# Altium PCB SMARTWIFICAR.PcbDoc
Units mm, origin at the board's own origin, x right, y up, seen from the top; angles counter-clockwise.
Board outline 20 x 36.25 mm, 2 copper layers (Top Layer, Bottom Layer); 33 components, 21 nets, 122 pads, 17 vias.
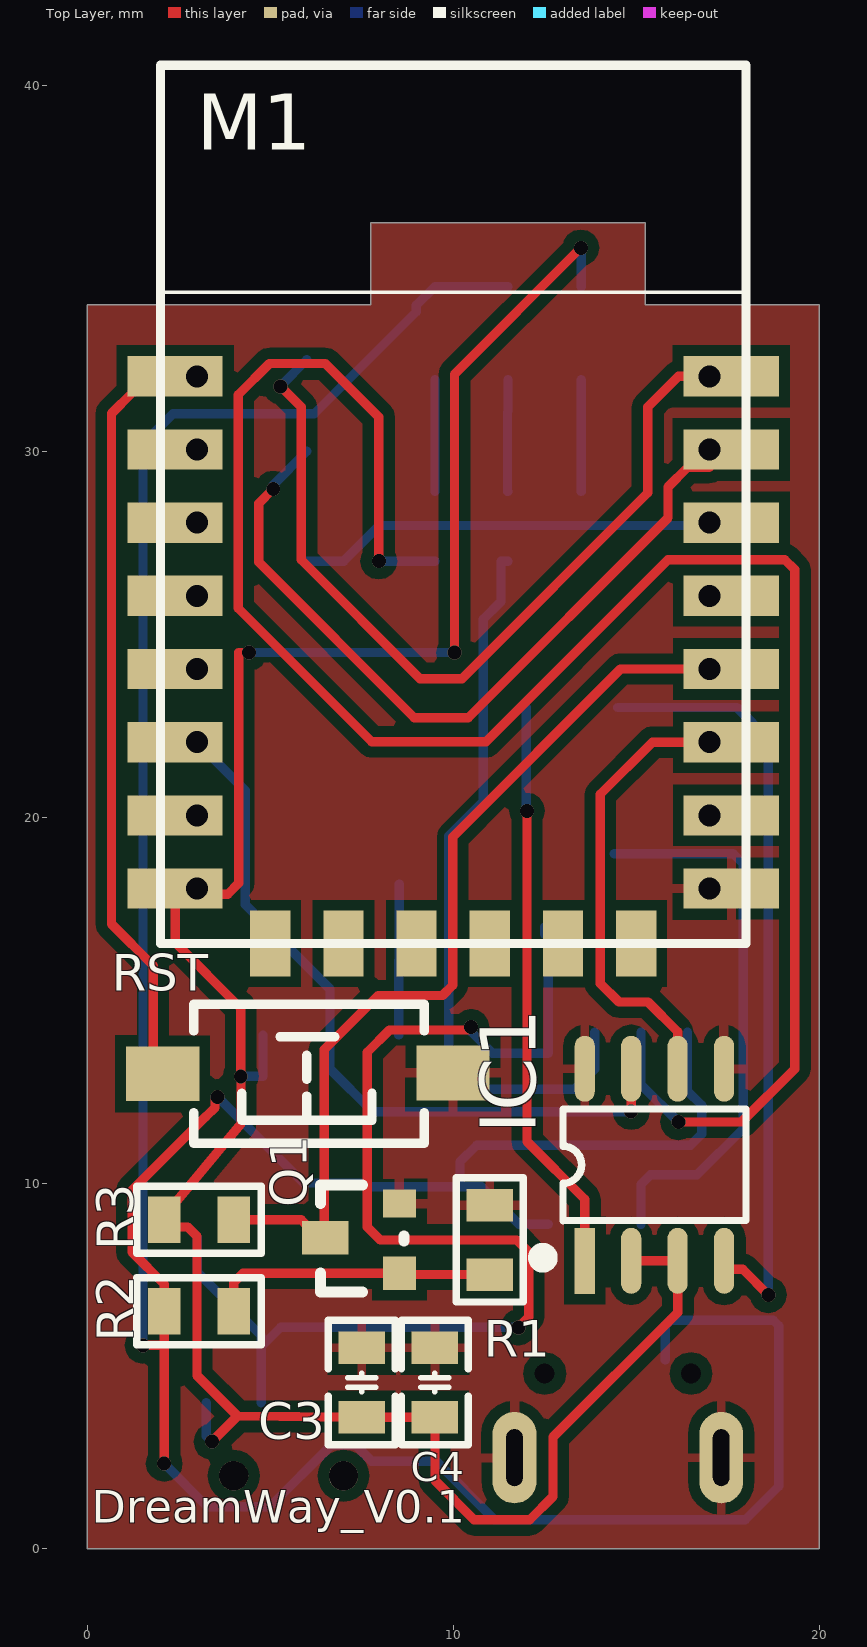
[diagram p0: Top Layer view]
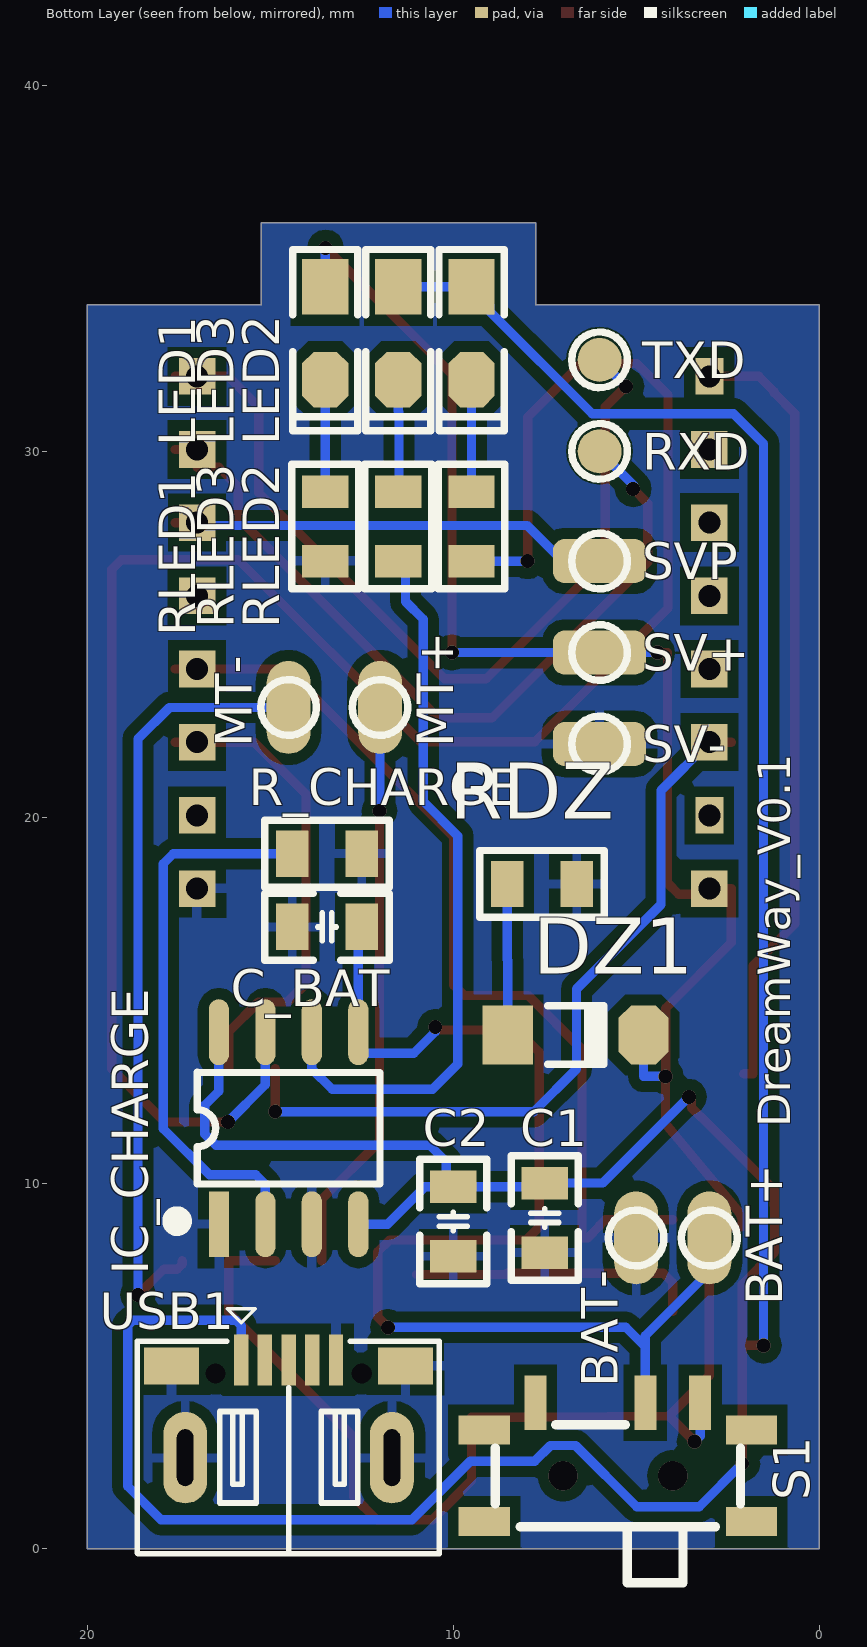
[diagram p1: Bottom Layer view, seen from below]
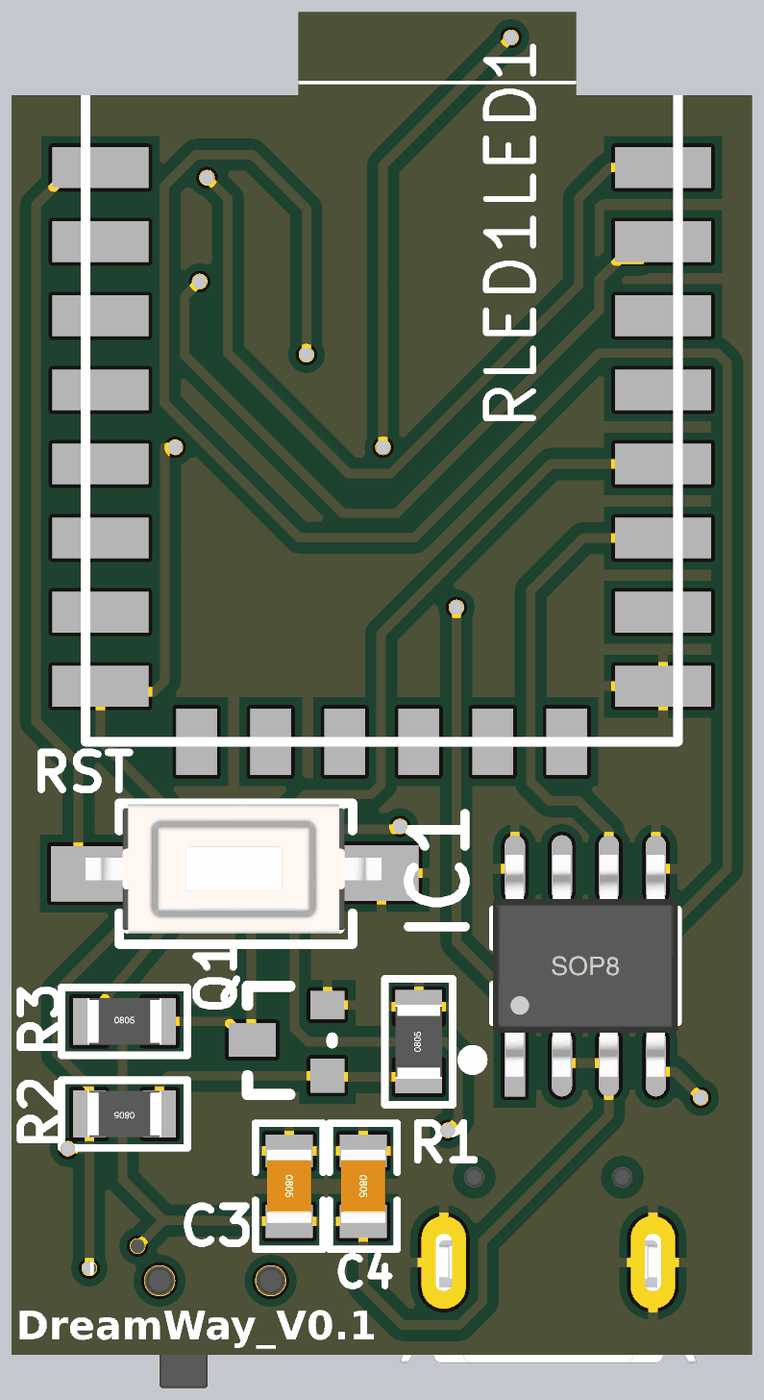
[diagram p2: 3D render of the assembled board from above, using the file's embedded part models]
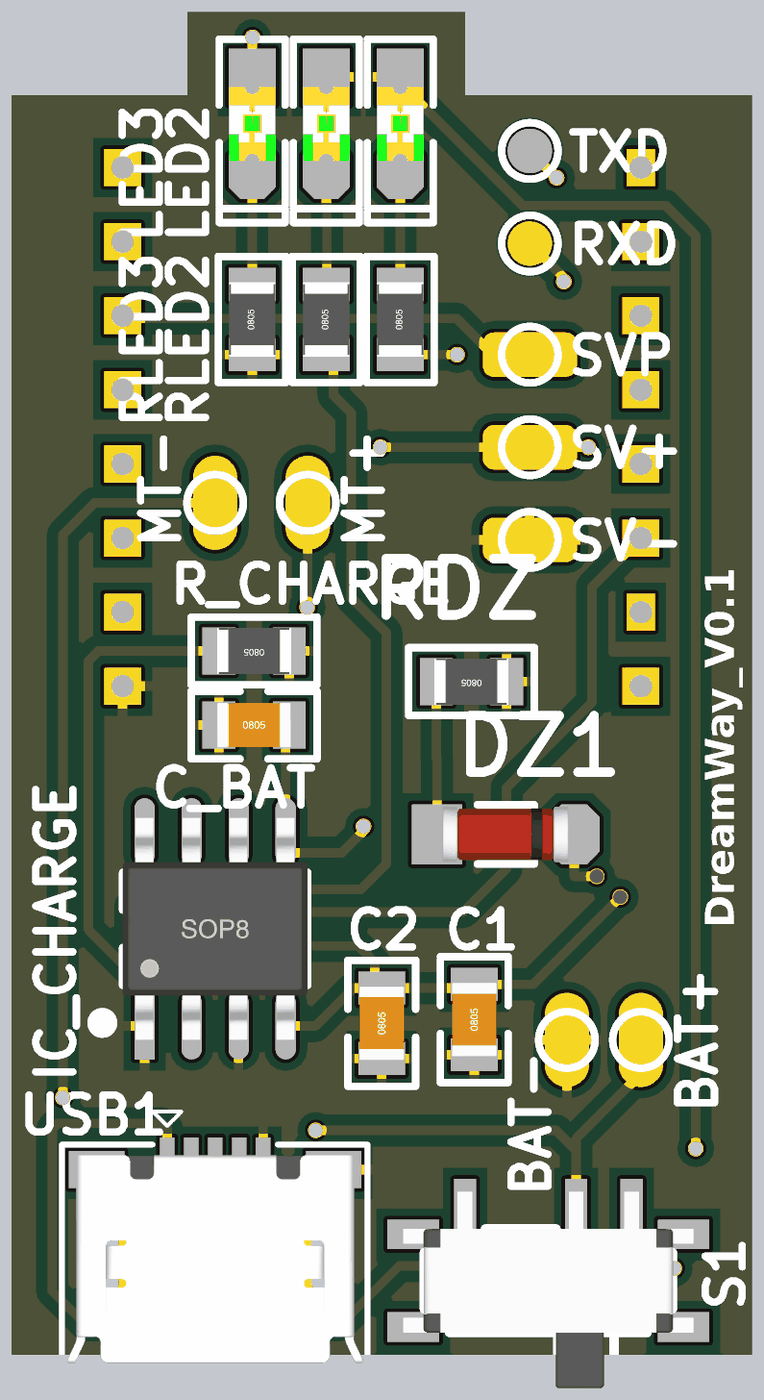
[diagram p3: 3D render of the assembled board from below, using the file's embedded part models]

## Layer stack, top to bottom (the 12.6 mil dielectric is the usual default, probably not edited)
Top Solder: solder mask 0.0102, Solder Resist, Dk 3.5
Top Layer: signal copper 0.0356
Dielectric 1: dielectric 0.32, FR-4, Dk 4.8
Bottom Layer: signal copper 0.0356
Bottom Solder: solder mask 0.0102, Solder Resist, Dk 3.5

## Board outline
0,0 0,34 7.75,34 7.75,36.25 15.25,36.25 15.25,34 20,34 20,0

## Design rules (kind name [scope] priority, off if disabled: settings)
Clearance [All] p1: gap=0.3 ignorepadtopadclearanceinfootprint=FALSE
HoleSize [All] p1: absolutevalues=TRUE maxlimit=2.54 minlimit=0.3 maxpercent=80.000 minpercent=20.000
PlaneConnect [All] p1: planeconnectstyle=Relief reliefexpansion=0.508 reliefentries=4 reliefconductorwidth=0.3 reliefairgap=0.3
PolygonConnect [All] p1: connectstyle=Relief reliefconductorwidth=0.254 reliefentries=4 polygonreliefangle="90 Angle" airgapwidth=0.3
RoutingVias [All] p1: holewidth=0.381 width=0.381 viastyle="Through Hole" minholewidth=0.381 minwidth=0.381 maxholewidth=0.711 maxwidth=1.27
SolderMaskExpansion [All] p1: expansion=0.102 istentingtop=FALSE
UnRoutedNet [All] p1: checkbadconnections=TRUE
Width [All] p1: maxlimit=0.508 minlimit=0.152 preferedwidth=0.254
27 further rules are at their usual default settings.

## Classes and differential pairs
component class Motor: IC1
component class IO_CONN: BAT+ BAT- MT+ RXD SV+ SV- SVP TXD
component class Control: M1 Q1 R1 R2 R3 RST
component class Charge: C1 C2 C3 C4 C_BAT DZ1 IC_CHARGE LED1 LED2 LED3 R_CHARGE RDZ RLED1 RLED2 RLED3 S1 USB1

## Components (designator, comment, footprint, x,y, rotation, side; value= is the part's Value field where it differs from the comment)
BAT+ "TEST" "TEST 1.2"#1 3,8.5 r180 bottom
BAT- "TEST" "TEST 1.2"#1 5,8.5 r180 bottom
C1 "106" "C 0805_L" 7.5,9.05 r90 bottom
C2 "104" "C 0805_L" 10,8.95 r90 bottom
C3 "106" "C 0805_L" 7.5,4.55 r270 top
C4 "104" "C 0805_L" 9.5,4.55 r270 top
C_BAT "106" "C 0805_L" 13.45,17 r180 bottom
DZ1 "ZMM3V3" "MINI_MELF (LL34)" 6.655,14.05 r180 bottom
IC1 "L9110" SOP8_N 15.5,10.5 r90 top
IC_CHARGE "TP4056" SOP8_N 14.5,11.5 r90 bottom
LED1 "BLUE" "LED 0805B" 13.5,33.23 r270 bottom
LED2 "RED" "LED 0805R" 9.5,33.23 r270 bottom
LED3 "GREEN" "LED 0805G" 11.5,33.23 r270 bottom
M1 "ESP-12E&F Module F" "ESP-12E&F Module" 10,24.3 r0 top
MT+ "TEST" "TEST 1.2"#1 12,23 r0 bottom
MT- "TEST" "TEST 1.2"#1 14.5,23 r180 bottom
Q1 "BCP68" SOT-23 5.477,6.322 r90 top
R1 "10K" "R 0805_L" 11,8.45 r90 top
R2 "10K" "R 0805_L" 3.05,6.5 r180 top
R3 "10K" "R 0805_L" 3.05,9 r0 top
R_CHARGE "1.2K" "R 0805_L" 13.45,19 r0 bottom
RDZ "1.2K" "R 0805_L" 7.575,18.175 r0 bottom
RLED1 "1.2K" "R 0805_L" 13.5,27.95 r90 bottom
RLED2 "1.2K" "R 0805_L" 9.5,27.95 r90 bottom
RLED3 "1.2K" "R 0805_L" 11.5,27.95 r90 bottom
RST "3x6x5" "TSW SMD-3*6*2.5" 6,12.987 r180 top
RXD "TEST" "TEST 1.2"#2 6,30 r0 bottom
S1 "SS-12F23" MSK-12C01-07 5.5,2 r180 bottom
SV+ "TEST" "TEST 1.2"#3 6,24.5 r270 bottom
SV- "TEST" "TEST 1.2"#3 6,22 r270 bottom
SVP "TEST" "TEST 1.2"#3 6,27 r270 bottom
TXD "TEST" "TEST 1.2"#4 6,32.5 r0 bottom
USB1 "USB-5P" USB-MICRO_B 14.5,2.5 r180 bottom

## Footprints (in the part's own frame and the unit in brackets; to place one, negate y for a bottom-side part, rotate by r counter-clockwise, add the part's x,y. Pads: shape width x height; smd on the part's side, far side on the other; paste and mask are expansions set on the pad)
"C 0805_L" [mil] "无极性贴片电容                                        淘宝ID:黄晶宝石"
  rect 35x50 smd: 1(-37.4,0) 2(37.4,0)
  silkscreen extent -67,-36 67,36, body extent -39,-24 39,24, height 20
"ESP-12E&F Module" [mm]
  rect 2.6x1.1 smd: 1(-7.6,7.75) 2(-7.6,5.75) 3(-7.6,3.75) 4(-7.6,1.75) 5(-7.6,-0.25) 6(-7.6,-2.25) 7(-7.6,-4.25) 8(-7.6,-6.25) 15(7.6,-6.25) 16(7.6,-4.25) 17(7.6,-2.25) 18(7.6,-0.25) 19(7.6,1.75) 20(7.6,3.75) 21(7.6,5.75) 22(7.6,7.75)
  rect 0.762x1 hole 0.6: 1(-7,7.75) 7(-7,-4.25)
  rect 0.762x1 / inner rect 0.762x1 / far side rect 1x1 hole 0.6: 2(-7,5.75) 3(-7,3.75) 4(-7,1.75) 5(-7,-0.25) 6(-7,-2.25) 8(-7,-6.25) 15(7,-6.25) 16(7,-4.25) 17(7,-2.25) 18(7,-0.25) 19(7,1.75) 20(7,3.75) 21(7,5.75) 22(7,7.75)
  rect 1.1x1.8 smd: 9(-5,-7.75) 10(-3,-7.75) 11(-1,-7.75) 12(1,-7.75) 13(3,-7.75) 14(5,-7.75)
  silkscreen extent -8,-7.75 8,16.25
"LED 0805B" [mil] "蓝色0805LED                                    淘宝ID:黄晶宝石"
  rect 60x50 smd: 1(-50,0)
  oct 60x50 smd: 2(50,0)
  silkscreen extent -90,-35 105,35, body extent -39,-25 39,25, height 32
"LED 0805G" [mil] "绿色0805LED                              淘宝ID:黄晶宝石"
  rect 60x50 smd: 1(-50,0)
  oct 60x50 smd: 2(50,0)
  silkscreen extent -90,-35 105,35, body extent -39,-25 39,25, height 32
"LED 0805R" [mil] "红色0805LED                                       淘宝ID:黄晶宝石"
  rect 60x50 smd: 1(-50,0)
  oct 60x50 smd: 2(50,0)
  silkscreen extent -90,-35 105,35, body extent -39,-25 39,25, height 32
"MINI_MELF (LL34)" [mm] "1.5*3.4mm(直径，脚距）"
  rect 1.37x1.62 smd: 1(-1.855,0)
  oct 1.37x1.62 smd: 2(1.855,0)
  silkscreen extent -0.76,-0.8 0.78,0.8, body extent -1.7,-0.75 1.7,0.75, height 1.5
MSK-12C01-07 [mm] "6.7*2.8*1.5mm(长宽高）      淘宝ID:黄晶宝石"
  rect 1.4x0.8 smd: 0(-3.65,-1.25) 0(-3.65,1.25) 0(3.65,-1.25) 0(3.65,1.25)
  rect 0.6x1.5 smd: 1(-2.25,1.996) 2(0.75,1.996) 3(2.25,1.996)
  round 0.8 hole 0.8: " "(-1.5,0) " "(1.5,0)
  silkscreen extent -3.35,-2.92 3.35,1.4, body extent -3.92,-2.9 3.92,2.4, height 1.5
"R 0805_L" [mil] "1/8W贴片电阻"
  rect 35x50 smd: 1(-37.41,0) 2(37.4,0)
  silkscreen extent -67,-36 67,36, body extent -39,-25 39,25, height 20
SOP8_N [mm] "5*6*1.8mm（长宽高）封装库来自淘宝卖家 ID：黄晶宝石"
  rect 1.8x0.55 smd: 1(-2.625,1.905)
  oval 1.8x0.55 smd: 2(-2.625,0.635) 3(-2.625,-0.635) 4(-2.625,-1.905) 5(2.625,-1.905) 6(2.625,-0.635) 7(2.625,0.635) 8(2.625,1.905)
  silkscreen extent -2.69,-2.5 1.52,3.2, body extent -3,-2.5 3,2.5, height 1.9
SOT-23 [mil] "封装库来自淘宝卖家 ID：黄晶宝石"
  rect 36x36 smd: 1(47.75,-120.28)
  rect 30x36 smd: 2(122.75,-120.28)
  rect 36x50 smd: 3(85.75,-40.28)
  silkscreen extent 28,-125 143,-35
"TEST 1.2"#1 [mm] "测试点1.2mm"
  oval 1.2x2.54 smd paste-1.2: 1(0,0)
  silkscreen extent -0.76,-0.76 0.76,0.76
"TEST 1.2"#2 [mm] "测试点1.2mm"
  round 1.2 smd paste-1.2: 1(0,0)
  silkscreen extent -0.76,-0.76 0.76,0.76
"TEST 1.2"#3 [mm] "测试点1.2mm"
  rrect50% 1.2x2.54 smd paste-1.2: 1(0,0)
  silkscreen extent -0.76,-0.76 0.76,0.76
"TEST 1.2"#4 [mm] "测试点1.2mm"
  round 1.2 smd paste+0: 1(0,0)
  silkscreen extent -0.76,-0.76 0.76,0.76
"TSW SMD-3*6*2.5" [mm] "3*6*2.5mm"
  rect 2x1.5 smd: 1(-3.996,-0.02) 2(3.937,0)
  silkscreen extent -3.21,-1.9 3.09,1.9, body extent -4,-1.88 4,1.62, height 2.59
USB-MICRO_B [mm] "micro型USB ，5.9*8.2*2.5mm 淘宝ID:黄晶宝石   店铺网址:https://shop463601444.taobao.com"
  round 0 hole 0.55 unplated: 0(-2,2.294) 0(2,2.294)
  rect 0.394x1.4 smd: 1(-1.295,2.667) 2(-0.648,2.667) 3(0,2.667) 4(0.648,2.667) 5(1.295,2.667)
  rect 1.5x1 smd: 5(-3.2,2.5) 5(3.2,2.5)
  oval 1.2x2.5 hole 0.45 slot 1.55 at 90 deg: 5(-2.825,-0.006) 5(2.825,-0.006)
  silkscreen extent -4.14,-2.63 4.11,4.06, body extent -4,-2.72 4,2.88, height 2.8

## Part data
BAT+ BAT- MT+ MT- RXD SV+ SV- SVP TXD: "测试点"
C1 C2 C3 C4 C_BAT: library part C, "贴片电容"
DZ1: library part 1N4619, "3V/0.5W稳压管"
IC1: "直流电机控制芯片"
IC_CHARGE: "锂电池充电管理"
LED1 LED2 LED3: library part LED-SMD, "贴片LED"
M1: library part "ESP-12E&F Module", "ESP-12E&F Module"
Q1: "NPN三极管"
R1 R2 R3 R_CHARGE RDZ RLED1 RLED2 RLED3: library part R, "贴片电阻"
RST: library part "TSW 3x6", "3x6轻触开关"
S1: library part SSW-1P, "1路波动开关"
USB1: "微型USB母座"

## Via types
v1: diameter 0.381, hole 0.381, Top Layer to Bottom Layer, 17 vias

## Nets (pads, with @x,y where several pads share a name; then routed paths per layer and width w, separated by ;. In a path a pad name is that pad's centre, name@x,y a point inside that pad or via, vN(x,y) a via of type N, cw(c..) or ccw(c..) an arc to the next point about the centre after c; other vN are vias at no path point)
3V3: C3.2 C4.2 DZ1.2 IC1.2 IC1.3 LED1.1 M1.8 R3.1 S1.3 SV+.1 | length 68.9
  Top Layer w0.254: v1(3.405,2.935) 4.104,3.633 ; v1(4.421,24.499) 4.142,24.499 4.142,18.2 3.837,17.895 3,17.895 3,18.05 2.4,18.05 2.4,16.575 4.193,14.782 v1(4.193,12.917) 4.2,12.909 4.2,11.621 2.182,9.2 R3.1 2.1,8.802 2.745,8.802 2.999,8.548 2.999,4.738 4.104,3.633 ; v1(10.035,24.5) 10.035,32.108 v1(13.489,35.563) ; IC1.2 IC1.3 16.135,6.465 12.727,3.057 12.727,1.436 12.092,0.801 10.568,0.801 9.5,1.869 C4.2 C3.2 4.104,3.633
  Bottom Layer w0.254: S1.3 3.25,3.09 v1(3.405,2.935) ; v1(4.193,12.917) 4.8,12.917 DZ1.2 ; v1(4.421,24.499) SV+.1 v1(10.035,24.5) ; v1(13.489,35.563) 13.5,35.552 LED1.1
BAT+: BAT+.1 C_BAT.2 IC_CHARGE.5 S1.2 | length 33.2
  Top Layer w0.254: v1(10.492,14.263) 10.416,14.187 8.257,14.187 7.647,13.577 7.647,8.802 8.003,8.446 11.737,8.446 12.062,8.121 12.062,6.338 v1(11.783,6.059)
  Bottom Layer w0.254: BAT+.1 3,7.58 4.75,5.83 4.75,5.524 ; S1.2 4.75,5.524 ; v1(10.492,14.263) 10.492,14.136 11.076,13.552 12.595,13.552 IC_CHARGE.5 12.595,16.708 12.5,16.803 C_BAT.2 ; v1(11.783,6.059) 5.285,6.059 4.75,5.524
BAT-: BAT-.1 C1.1 C2.1 C3.1 C4.1 C_BAT.1 IC1.5 IC1.8 IC_CHARGE.1 IC_CHARGE.3 M1.15 Q1.2 R1.2 R_CHARGE.1 RDZ.1 RLED1.1 RST.1 SV-.1 USB1.5
NetDZ1_1: DZ1.1 RDZ.2 | length 4.1
  Bottom Layer w0.254: DZ1.1 8.51,16.092 8.525,16.107 RDZ.2
NetIC1_1: IC1.1 MT+.1 | length 15.8
  Top Layer w0.254: v1(12.016,20.175) 12.016,11.139 13.595,9.56 IC1.1
  Bottom Layer w0.254: MT+.1 12,20.191 v1(12.016,20.175)
NetIC1_4: IC1.4 MT-.1 | length 21.3
  Top Layer w0.254: IC1.4 17.405,7.782 17.542,7.645 17.912,7.645 v1(18.614,6.943)
  Bottom Layer w0.254: MT-.1 17.757,23 18.614,22.143 v1(18.614,6.943)
NetIC1_6: IC1.6 M1.17 | length 13
  Top Layer w0.254: IC1.6 16.135,14.136 15.321,14.95 14.529,14.95 14.022,15.457 14.022,20.625 15.448,22.05 17,22.05 17.299,22.05 M1.17@17.6,22.05
NetIC1_7: IC1.7 M1.6 | length 20.9
  Top Layer w0.254: M1.6@2.4,22.05 M1.6@3,22.05 ; v1(14.865,11.952) IC1.7
  Bottom Layer w0.254: M1.6@3,22.05 4.32,20.73 4.32,17.616 6.631,15.304 6.631,13.12 7.799,11.952 v1(14.865,11.952)
NetIC_CHARGE_2: IC_CHARGE.2 R_CHARGE.2 | length 15.4
  Bottom Layer w0.254: R_CHARGE.2 17.654,19 17.927,18.727 17.927,11.487 16.664,10.224 15.394,10.224 15.135,9.965 IC_CHARGE.2
NetIC_CHARGE_6: IC_CHARGE.6 RLED3.1 | length 20
  Bottom Layer w0.254: RLED3.1 11.305,27 11.305,25.896 10.822,25.414 10.822,20.435 9.874,19.487 9.874,13.255 10.568,12.561 13.306,12.561 13.865,13.12 IC_CHARGE.6
NetIC_CHARGE_7: IC_CHARGE.7 RLED2.1 | length 55.3
  Top Layer w0.254: v1(7.966,27) 7.966,30.937 6.504,32.399 4.98,32.399 4.127,31.546 4.127,25.708 7.774,22.061 10.894,22.061 15.873,27.039 19.065,27.039 19.331,26.773 19.331,13.12 17.881,11.67 v1(16.156,11.67)
  Bottom Layer w0.254: v1(7.966,27) RLED2.1 ; IC_CHARGE.7 15.135,12.691 v1(16.156,11.67)
NetLED1_2: LED1.2 RLED1.2 | length 3.1
  Bottom Layer w0.254: RLED1.2 LED1.2
NetLED2_2: LED2.2 RLED2.2 | length 3.1
  Bottom Layer w0.254: RLED2.2 LED2.2
NetLED3_2: LED3.2 RLED3.2 | length 3.1
  Bottom Layer w0.254: RLED3.2 11.482,28.9 11.482,31.078 11.5,31.095 LED3.2
NetM1_1: M1.1 RST.2 | length 21.6
  Top Layer w0.254: RST.2 1.805,12.987 1.805,15.939 0.662,17.082 0.662,31.037 1.227,31.602 1.227,31.627 1.65,32.05 2.4,32.05 M1.1@3,32.05
NetM1_18: M1.18 Q1.3 R3.2 | length 25.7
  Top Layer w0.254: R3.2 5.843,9 5.992,8.851 5.992,8.83 6.322,8.5 Q1.3 ; Q1.3@6.479,8.5 6.479,13.653 7.952,15.127 9.704,15.127 9.984,15.406 9.984,19.462 14.572,24.05 17,24.05 17.299,24.05 M1.18@17.6,24.05
NetM1_20: M1.20 SVP.1 | length 12
  Top Layer w0.254: M1.20@17,28.05 M1.20@17.6,28.05
  Bottom Layer w0.254: SVP.1 7.005,27 7.98,27.975 16.925,27.975 M1.20@17,28.05
NetM1_21: M1.21 RXD.1 | length 22.1
  Top Layer w0.254: v1(5.082,28.974) 4.681,28.574 4.681,26.977 8.937,22.721 10.413,22.721 15.873,28.181 15.873,29.027 16.41,29.564 17,29.564 17,30.05 M1.21@17.6,30.05
  Bottom Layer w0.254: v1(5.082,28.974) 5.082,29.082 RXD.1
NetM1_22: M1.22 TXD.1 | length 23.9
  Top Layer w0.254: v1(5.278,31.778) 5.843,31.213 5.843,27.04 9.095,23.788 10.239,23.788 15.319,28.868 15.319,31.213 16.156,32.05 17,32.05 17.299,32.05 M1.22@17.6,32.05
  Bottom Layer w0.254: v1(5.278,31.778) TXD.1
NetQ1_1: Q1.1 R1.1 R2.1 | length 7.9
  Top Layer w0.254: R2.1 4,7.278 4.257,7.535 Q1.1 8.567,7.5 R1.1
USB5V: C1.2 C2.2 IC_CHARGE.4 IC_CHARGE.8 LED2.1 LED3.1 R2.2 USB1.1 | length 97.2
  Top Layer w0.254: v1(1.519,5.566) 2.1,5.566 ; v1(2.1,2.335) 2.1,5.566 ; v1(3.558,12.358) 3.558,12.324 3.49,12.256 3.49,12.06 3.24,11.81 3.227,11.81 1.228,9.812 1.228,9.403 1.221,9.396 1.221,8.116 2.1,7.237 R2.2 2.1,5.566
  Bottom Layer w0.254: v1(1.519,5.566) 1.519,30.207 2.338,31.027 6.202,31.027 8.992,33.817 8.992,33.992 LED2.1 LED3.1 ; v1(2.1,2.335) 3.278,1.157 4.987,1.157 6.657,2.827 7.343,2.827 7.768,2.401 9.527,2.401 11.127,0.801 17.985,0.801 18.899,1.715 18.899,6.101 18.75,6.25 15.944,6.25 15.795,6.101 USB1.1 ; v1(3.558,12.358) 5.916,10 C1.2 7.6,9.9 8.788,9.9 C2.2 C2.2@10.187,9.9 ; IC_CHARGE.4 11.796,8.875 10.771,9.9 C2.2@10.187,9.9 ; IC_CHARGE.8 16.405,12.51 16.791,12.124 16.791,11.342 16.486,11.037 10.644,11.037 10.187,10.58 C2.2@10.187,9.9
pads on no net: "S1. " M1.2 M1.3 M1.4 M1.5 M1.7 M1.9 M1.10 M1.11 M1.12 M1.13 M1.14 M1.16 M1.19 S1.0 S1.1 USB1.0 USB1.2 USB1.3 USB1.4

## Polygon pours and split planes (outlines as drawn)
BAT- on Bottom Layer "BAT-_L02_P011" (solid, pour order 11): 0,34 7.75,34 7.75,36.25 15.25,36.25 15.25,34 20,34 20,0 0,0
BAT- on Bottom Layer "BAT-_L02_P001" (solid, pour order 1): 0,34 7.75,34 7.75,36.25 15.25,36.25 15.25,34 20,34 20,0 0,0
BAT- on Bottom Layer "BAT-_L02_P000" (solid, pour order 0): 0,0 20,0 20,34 15.25,34 15.25,36.25 7.75,36.25 7.75,34 0,34
BAT- on Top Layer "BAT-_L01_P010" (solid, pour order 10): 0,34 7.75,34 7.75,36.25 15.25,36.25 15.25,34 20,34 20,0 0,0
no net on Top Layer "NONET_L01_P009" (solid, pour order 9): 0,34

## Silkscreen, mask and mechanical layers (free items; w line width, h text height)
Top Overlay:
  text "DreamWay_V0.1" at 0.125,0.416 h1.52
Bottom Overlay:
  text "DreamWay_V0.1" at 0.491,11.525 h1.52 r270
Mechanical 1:
  lines w0.254: 0,0 20,0 20,13 20,34 15.25,34 15.25,36.25 7.75,36.25 7.75,34 0,34 0,0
